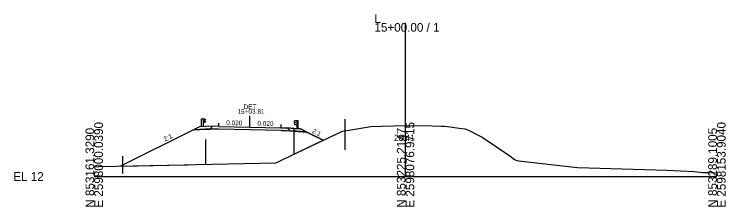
# Model space of a CAD drawing. Extents: x -26 to 1203, y -10 to 9526.
# Drawn here: x -25.7 to 202.8, y 4990.3 to 5052 of the extents above; entities that cross this region are included whole.
import ezdxf

# ---------------------------------------------------------------- set-up
doc = ezdxf.new("R2010")
doc.units = 0
for name, color, linetype in [('Exist Cross Section Cell', 7, 'Continuous'), ('Exist XS Center Line Elevation Label', 7, 'Continuous'), ('Exist XS Ground Line', 7, 'Continuous'), ('Prop XS Alignment Label', 7, 'Continuous'), ('Prop XS Earthwork Shape', 7, 'Continuous'), ('Prop XS EOT Tick Mark', 7, 'Continuous'), ('Prop XS Exc Vertical Line 1', 7, 'Continuous'), ('Prop XS Exc Vertical Line 2', 7, 'Continuous'), ('Prop XS Finish Grade', 7, 'Continuous'), ('Prop XS Finish Grade Earthwork', 7, 'Continuous'), ('Prop XS Finish Grade Paved Shoulder', 7, 'Continuous'), ('Prop XS Finish Grade Pavement', 7, 'Continuous'), ('Prop XS Guardrail', 7, 'Continuous'), ('Prop XS Pvmt Edge Slope', 7, 'Continuous'), ('Prop XS SE Text', 7, 'Continuous'), ('Prop XS Side Slope Text', 7, 'Continuous'), ('Prop XS Station Labels', 7, 'Continuous'), ('Prop XS Subgrade Earthwork', 7, 'Continuous'), ('Scratch_Level_1', 7, 'Continuous'), ('Scratch_Level_2', 7, 'Continuous')]:
    doc.layers.add(name, color=color, linetype=linetype)

msp = doc.modelspace()

# ---------------------------------------------------------------- linework, layer by layer
at = {"layer": 'Exist Cross Section Cell'}
for p, q in [((100, 5000), (100, 5049.23)), ((0, 5000), (100, 5000)), ((100, 5000), (200, 5000))]:
    msp.add_line(p, q, dxfattribs=at)
at = {"layer": 'Exist XS Ground Line'}
for p, q in [((92.11, 5016.14), (100.05, 5016.41)), ((100.05, 5016.41), (108.51, 5016.24)), ((63.21, 5006.7), (79.74, 5014.55)), ((79.74, 5014.55), (82.42, 5014.99)), ((82.42, 5014.99), (88.81, 5016.02)), ((88.81, 5016.02), (92.11, 5016.14)), ((108.51, 5016.24), (111.49, 5016.18)), ((111.49, 5016.18), (112.51, 5016.15)), ((112.51, 5016.15), (113.42, 5016.02)), ((113.42, 5016.02), (117.21, 5015.55)), ((117.21, 5015.55), (118.98, 5015.3)), ((118.98, 5015.3), (120.22, 5014.91)), ((120.22, 5014.91), (123.15, 5013.37)), ((123.15, 5013.37), (124.59, 5012.63)), ((124.59, 5012.63), (133.48, 5006.62)), ((59.03, 5004.66), (63.21, 5006.7)), ((133.48, 5006.62), (135.03, 5005.51)), ((135.03, 5005.51), (135.76, 5005.1)), ((135.76, 5005.1), (137.2, 5004.94)), ((137.2, 5004.94), (155.17, 5002.89)), ((0, 5003.15), (1.64, 5003.16)), ((1.64, 5003.16), (28.84, 5003.7)), ((28.84, 5003.7), (30.11, 5003.72)), ((30.11, 5003.72), (32.79, 5003.84)), ((32.79, 5003.84), (58.37, 5004.4)), ((58.37, 5004.4), (59.03, 5004.66)), ((155.17, 5002.89), (183.94, 5002)), ((183.94, 5002), (192.74, 5001.64)), ((192.74, 5001.64), (194.5, 5001.37)), ((194.5, 5001.37), (195.37, 5001.27)), ((195.37, 5001.27), (197.31, 5001.25)), ((197.31, 5001.25), (199.42, 5001.22)), ((199.42, 5001.22), (200, 5001.26))]:
    msp.add_line(p, q, dxfattribs=at)
at = {"layer": 'Prop XS Earthwork Shape'}
msp.add_lwpolyline([(31.88, 5014.99), (9.07, 5003.59), (9.07, 5003.31), (28.84, 5003.7), (30.11, 5003.72), (32.79, 5003.84), (58.37, 5004.4), (59.03, 5004.66), (63.21, 5006.7), (73.56, 5011.62), (68.28, 5014.26), (66.23, 5014.42), (64.94, 5014.52), (64.01, 5014.54), (60, 5014.74), (50, 5014.94), (40, 5015.14), (38, 5015.18), (37.1, 5015.2), (35.76, 5015.15)], close=True, dxfattribs=at)
at = {"layer": 'Prop XS EOT Tick Mark'}
for p, q in [((40, 5016.06), (40, 5017.06)), ((60, 5015.66), (60, 5016.66))]:
    msp.add_line(p, q, dxfattribs=at)
at = {"layer": 'Prop XS Exc Vertical Line 1'}
msp.add_line((9.07, 5006.5), (9.07, 5000.93), dxfattribs=at)
at = {"layer": 'Prop XS Exc Vertical Line 2'}
msp.add_line((80.54, 5018.38), (80.54, 5008.6), dxfattribs=at)
at = {"layer": 'Prop XS Finish Grade'}
for p, q in [((33.76, 5015.93), (31.88, 5014.99)), ((35.76, 5016.01), (33.76, 5015.93)), ((38, 5016.1), (35.76, 5016.01)), ((62, 5015.62), (64.23, 5015.44)), ((64.23, 5015.44), (66.23, 5015.28)), ((66.23, 5015.28), (68.28, 5014.26))]:
    msp.add_line(p, q, dxfattribs=at)
at = {"layer": 'Prop XS Finish Grade Earthwork'}
for p, q in [((31.88, 5014.99), (8.49, 5003.29)), ((68.28, 5014.26), (73.56, 5011.62))]:
    msp.add_line(p, q, dxfattribs=at)
at = {"layer": 'Prop XS Finish Grade Paved Shoulder'}
for p, q in [((40, 5016.06), (38, 5016.1)), ((60, 5015.66), (62, 5015.62))]:
    msp.add_line(p, q, dxfattribs=at)
at = {"layer": 'Prop XS Finish Grade Pavement'}
for p, q in [((40, 5016.06), (50, 5015.86)), ((50, 5015.86), (60, 5015.66))]:
    msp.add_line(p, q, dxfattribs=at)
at = {"layer": 'Prop XS Guardrail'}
for p, q in [((34.44, 5018.46), (34.94, 5018.46)), ((34.44, 5015.96), (34.44, 5018.46)), ((34.94, 5018.46), (35.44, 5018.46)), ((34.94, 5018.46), (34.94, 5015.96)), ((35.44, 5017.32), (34.94, 5017.32)), ((35.44, 5018.46), (35.73, 5018.26)), ((35.73, 5018.14), (35.44, 5017.94)), ((35.44, 5017.94), (35.44, 5017.84)), ((35.44, 5017.84), (35.73, 5017.64)), ((35.73, 5017.52), (35.44, 5017.32)), ((35.73, 5018.26), (35.76, 5018.2)), ((35.76, 5018.2), (35.73, 5018.14)), ((35.73, 5017.64), (35.76, 5017.58)), ((35.76, 5017.58), (35.73, 5017.52)), ((64.26, 5017.64), (64.23, 5017.58)), ((64.23, 5017.58), (64.26, 5017.52)), ((64.26, 5017.02), (64.23, 5016.96)), ((64.23, 5016.96), (64.26, 5016.9)), ((64.55, 5017.84), (64.26, 5017.64)), ((64.26, 5017.52), (64.55, 5017.32)), ((64.55, 5017.22), (64.26, 5017.02)), ((64.26, 5016.9), (64.55, 5016.7)), ((65.05, 5017.84), (64.55, 5017.84)), ((64.55, 5017.32), (64.55, 5017.22)), ((64.55, 5016.7), (65.05, 5016.7)), ((65.55, 5017.84), (65.05, 5017.84)), ((65.05, 5017.84), (65.05, 5015.34)), ((65.55, 5015.34), (65.55, 5017.84))]:
    msp.add_line(p, q, dxfattribs=at)
at = {"layer": 'Prop XS Pvmt Edge Slope'}
for p, q in [((38, 5016.1), (37.1, 5015.2)), ((62, 5015.62), (62.94, 5014.68))]:
    msp.add_line(p, q, dxfattribs=at)
at = {"layer": 'Prop XS Side Slope Text'}
msp.add_line((50, 5015.86), (50, 5019.51), dxfattribs=at)
at = {"layer": 'Prop XS Subgrade Earthwork'}
for p, q in [((35.76, 5015.15), (31.88, 5014.99)), ((37.1, 5015.2), (35.76, 5015.15)), ((38, 5015.18), (37.1, 5015.2)), ((40, 5015.14), (38, 5015.18)), ((50, 5014.94), (40, 5015.14)), ((60, 5014.74), (50, 5014.94)), ((60, 5014.74), (62.94, 5014.68)), ((62.94, 5014.68), (68.28, 5014.26))]:
    msp.add_line(p, q, dxfattribs=at)
at = {"layer": 'Scratch_Level_1'}
for points in [[(33.76, 5015.93), (31.88, 5014.99), (35.76, 5015.15), (37.1, 5015.2), (38, 5016.1), (35.76, 5016.01)], [(62.94, 5014.68), (68.28, 5014.26), (66.23, 5015.28), (64.23, 5015.44), (62, 5015.62)]]:
    msp.add_lwpolyline(points, close=True, dxfattribs=at)
at = {"layer": 'Scratch_Level_2'}
for p, q in [((64.13, 5015.14), (64.13, 5007.14)), ((35.75, 5011.91), (35.75, 5003.91))]:
    msp.add_line(p, q, dxfattribs=at)

# ---------------------------------------------------------------- texts
at = {"layer": 'Exist Cross Section Cell'}
for s, p in [('L', (90, 5049.23)), ('15+00.00 / 1', (90, 5046.43)), ('EL 12', (-26, 4998.6))]:
    msp.add_text(s, height=2.8, dxfattribs=at).set_placement(p)
for s, p in [('E 2598000.0390', (2.8, 4990)), ('E 2598076.9715', (102.8, 4990)), ('E 2598153.9040', (202.8, 4990)), ('N 853161.3290', (0, 4990)), ('N 853225.2147', (100, 4990)), ('N 853289.1005', (200, 4990))]:
    msp.add_text(s, height=2.8, rotation=90, dxfattribs=at).set_placement(p)
at = {"layer": 'Exist XS Center Line Elevation Label'}
msp.add_text('28.41', height=2, dxfattribs=at).set_placement((96.27, 5011.41))
at = {"layer": 'Prop XS Alignment Label'}
msp.add_text('DET', height=1.5, dxfattribs=at).set_placement((47.97, 5021.61))
at = {"layer": 'Prop XS SE Text'}
for p in [(42.38, 5016.51), (52.38, 5016.31)]:
    msp.add_text('0.020', height=1.5, rotation=358.8542, dxfattribs=at).set_placement(p)
at = {"layer": 'Prop XS Side Slope Text'}
for rotation, p in [(333.4349, (69.84, 5014.12)), (26.5651, (22.73, 5011.18))]:
    msp.add_text('2:1', height=1.5, rotation=rotation, dxfattribs=at).set_placement(p)
at = {"layer": 'Prop XS Station Labels'}
msp.add_text('15+03.81', height=1.5, dxfattribs=at).set_placement((46.01, 5020.11))

doc.saveas('drawing.dxf')
